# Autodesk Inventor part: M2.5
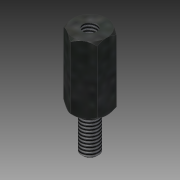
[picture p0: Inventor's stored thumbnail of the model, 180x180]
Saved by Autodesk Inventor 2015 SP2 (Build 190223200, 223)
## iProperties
Created: 2012-08
Part Number: M2.5
Material: Stahl
Document SubType Name: Modeling
Designer: rYan
Mass: 1.74537 g
Surface Area: 3.04272 cm^2
Volume: 0.22234 cm^3
Density: 7.85 g/cm^3
Appearance: Platte
Author: rYan
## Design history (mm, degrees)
sketch "Skizze1"
  geometry: L1 (2.5, -1.443)-(0, -2.887); L2 (0, -2.887)-(-2.5, -1.443); L3 (-2.5, -1.443)-(-2.5, 1.443); L4 (-2.5, 1.443)-(0, 2.887); L5 (0, 2.887)-(2.5, 1.443); L6 (2.5, 1.443)-(2.5, -1.443); L7 (0, 4.446)-(0, -4.446) reference; 2 further points
  constraints: 12 end point, 1 coincident, 1 parallel, 13 other
  dimensions: "SW" = 5 distance between parallel lines of L3 L6
extrude "Extrusion1" new body sketch "Skizze1" taper "d2" = 0 deg; stored distance "L" = 10
sketch "Skizze2"
  geometry: 2 further points
  constraints: 1 coincident
hole "Bohrung1" sketch "Skizze2" at (0, 0) diameter "d3" = 2.013; stored, may be unused: countersink angle "d7" = 90 deg, drill point angle "d9" = 118 deg; dims "d4" = 6, "d5" = 4, "d6" = 2, "l_" = 7
sketch "Skizze3"
  geometry: C1 r 1.25 at (0, 0); 1 further point
  constraints: 1 centre point, 1 coincident
  dimensions: "GA_" = 2.5 diameter of C1
extrude "Extrusion2" join sketch "Skizze3" taper "d13" = 0 deg; distance "A_" = 6
feature "Gewinde1" dims "d14" = 5, "d15" = 0
chamfer "Fase1" distance "d17" = 0.25; stored, may be unused: second distance "d18" = 2, angle "d19" = 45 deg
sketch "Skizze4"
  geometry: L1 (2.5, -1.443)-(2.5, 1.443) reference; C1 r 2.5 at (0, 0); 1 further point
  constraints: 1 centre point, 1 coincident, 1 tangent
sketch "Skizze5"
  geometry: L1 (-1.006, 5)-(1.006, 5) reference; L2 (-2.887, 5)-(-1.443, 5) reference; L3 (-1.443, 5)-(1.443, 5) reference; L4 (1.443, 5)-(2.887, 5) reference; L5 (2.887, 5)-(1.443, 5) reference; L6 (1.443, 5)-(-1.443, 5) reference; L7 (-1.443, 5)-(-2.887, 5) reference; L8 (2.887, 5)-(2.5, 5); L9 (2.5, 5)-(2.887, 4.613); L10 (2.887, 4.613)-(2.887, 5); L11 (0, 7)-(0, -7) reference; L12 (1.25, -5)-(-1.25, -5) reference; L13 (-1.443, -5)-(-2.887, -5) reference; L14 (-2.887, -5)-(-1.443, -5) reference; L15 (-1.443, -5)-(1.443, -5) reference; L16 (1.443, -5)-(2.887, -5) reference; L17 (2.887, -5)-(1.443, -5) reference; L18 (1.443, -5)-(-1.443, -5) reference; L19 (0, 5)-(0, -5); 2 further points; 1 other entity
  constraints: 8 end point, 1 collinear, 1 midpoint, 1 perpendicular, 1 point on line, 2 other
  dimensions: "d20" = 45 deg angle of L8 L9
revolve "Umdrehung1" sketch "Skizze5" stored, may be unused: angle "d21" = 90 deg
mirror "Spiegeln1"
node "Volumenkörper1"
node "Projizierte Kontur1"
node "Projizierte Kontur2"
